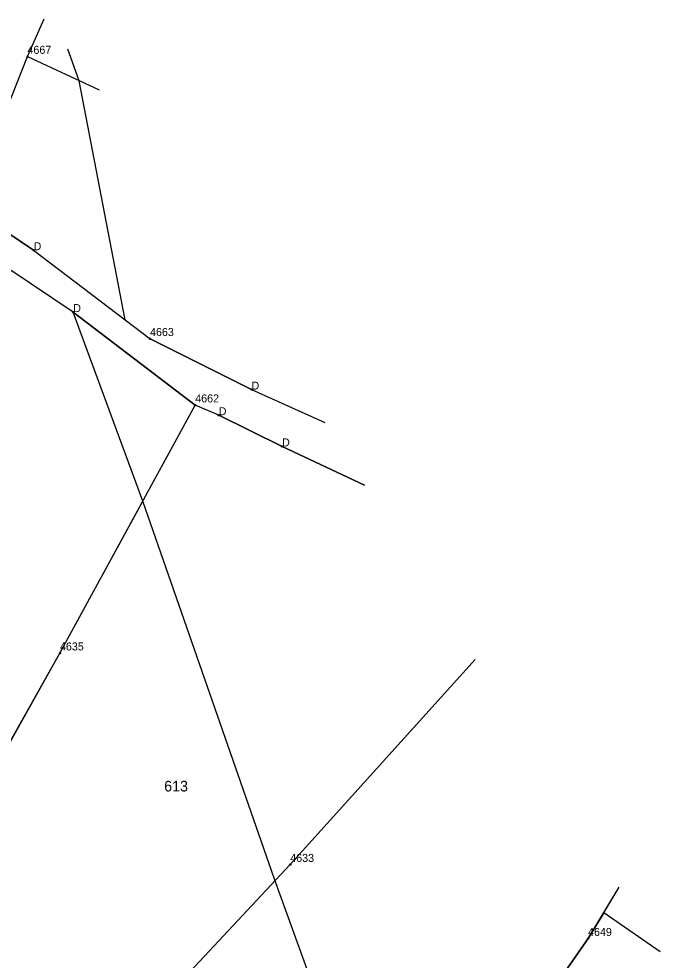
# Model space of a CAD drawing. Extents: x 7465393 to 7466459, y 5491258 to 5492404.
# Drawn here: x 7465838.7 to 7465928.8, y 5491869.8 to 5492002.2 of the extents above; entities that cross this region are included whole.
import ezdxf

# ---------------------------------------------------------------- set-up
doc = ezdxf.new("R2010")
doc.units = 0
for name, color, linetype in [('203-punkt graniczny', 7, 'Continuous'), ('203-punkt graniczny-Atr103', 7, 'Continuous'), ('211-numer działki ewidencyjnej', 7, 'Continuous'), ('217-kontur klasyfikacyjny', 7, 'Continuous'), ('218-kontur użytku gruntowego', 7, 'Continuous'), ('219-działka ewidencyjna', 7, 'Continuous')]:
    doc.layers.add(name, color=color, linetype=linetype)

# ---------------------------------------------------------------- blocks, each defined once
blk = doc.blocks.new('203')
blk.add_circle((0, 0), 0.09)

msp = doc.modelspace()

# ---------------------------------------------------------------- linework, layer by layer
at = {"layer": '217-kontur klasyfikacyjny'}
for points in [[(7465847.17, 5491993.46), (7465845.56, 5491997.89)], [(7465853.64, 5491959.84), (7465847.17, 5491993.46)], [(7465831.2, 5491976.07), (7465840.77, 5491969.64)], [(7465846.34, 5491960.94), (7465828.16, 5491973.13)], [(7465840.77, 5491969.64), (7465853.64, 5491959.84)], [(7465856.12, 5491934.36), (7465846.34, 5491960.94)], [(7465863.48, 5491947.86), (7465846.34, 5491960.94)], [(7465853.64, 5491959.84), (7465857.13, 5491957.19)], [(7465857.13, 5491957.19), (7465871.4, 5491950.04)], [(7465871.4, 5491950.04), (7465881.72, 5491945.4)], [(7465866.79, 5491946.44), (7465863.48, 5491947.86)], [(7465875.69, 5491942.06), (7465866.79, 5491946.44)], [(7465887.28, 5491936.61), (7465875.69, 5491942.06)], [(7465874.63, 5491881.21), (7465856.12, 5491934.36)], [(7465890.11, 5491838.48), (7465874.63, 5491881.21)]]:
    msp.add_lwpolyline(points, dxfattribs=at)
at = {"layer": '218-kontur użytku gruntowego'}
for points in [[(7465831.2, 5491976.07), (7465840.77, 5491969.64)], [(7465846.34, 5491960.94), (7465828.16, 5491973.13)], [(7465840.77, 5491969.64), (7465853.64, 5491959.84)], [(7465856.12, 5491934.36), (7465846.34, 5491960.94)], [(7465863.48, 5491947.86), (7465846.34, 5491960.94)], [(7465853.64, 5491959.84), (7465857.13, 5491957.19)], [(7465857.13, 5491957.19), (7465871.4, 5491950.04)], [(7465871.4, 5491950.04), (7465881.72, 5491945.4)], [(7465866.79, 5491946.44), (7465863.48, 5491947.86)], [(7465875.69, 5491942.06), (7465866.79, 5491946.44)], [(7465887.28, 5491936.61), (7465875.69, 5491942.06)], [(7465844.47, 5491912.99), (7465856.12, 5491934.36)], [(7465836.83, 5491899.38), (7465844.47, 5491912.99)], [(7465920.9, 5491876.48), (7465923.08, 5491880.07)], [(7465920.9, 5491876.48), (7465918.7, 5491872.85)], [(7465928.84, 5491870.98), (7465920.9, 5491876.48)], [(7465918.7, 5491872.85), (7465907.11, 5491856.18)]]:
    msp.add_lwpolyline(points, dxfattribs=at)
at = {"layer": '219-działka ewidencyjna'}
for points in [[(7465839.9, 5491996.87), (7465842.24, 5492002.17)], [(7465834.13, 5491982.39), (7465839.9, 5491996.87)], [(7465839.9, 5491996.87), (7465849.98, 5491992.2)], [(7465840.77, 5491969.64), (7465831.2, 5491976.07)], [(7465846.34, 5491960.94), (7465828.16, 5491973.13)], [(7465840.77, 5491969.64), (7465857.13, 5491957.19)], [(7465846.34, 5491960.94), (7465863.48, 5491947.86)], [(7465871.4, 5491950.04), (7465857.13, 5491957.19)], [(7465871.4, 5491950.04), (7465881.72, 5491945.4)], [(7465844.47, 5491912.99), (7465863.48, 5491947.86)], [(7465866.79, 5491946.44), (7465863.48, 5491947.86)], [(7465866.79, 5491946.44), (7465875.69, 5491942.06)], [(7465875.69, 5491942.06), (7465887.28, 5491936.61)], [(7465826.07, 5491880.19), (7465844.47, 5491912.99)], [(7465876.84, 5491883.26), (7465902.81, 5491912.1)], [(7465854.72, 5491859.63), (7465876.84, 5491883.26)], [(7465918.7, 5491872.85), (7465923.08, 5491880.07)], [(7465907.11, 5491856.18), (7465918.7, 5491872.85)]]:
    msp.add_lwpolyline(points, dxfattribs=at)

# ---------------------------------------------------------------- block references
at = {"layer": '203-punkt graniczny'}
for p in [(7465839.9, 5491996.87), (7465840.77, 5491969.64), (7465846.34, 5491960.94), (7465857.13, 5491957.19), (7465871.4, 5491950.04), (7465863.48, 5491947.86), (7465866.79, 5491946.44), (7465875.69, 5491942.06), (7465844.47, 5491912.99), (7465876.84, 5491883.26), (7465918.7, 5491872.85)]:
    msp.add_blockref('203', p, dxfattribs=at)

# ---------------------------------------------------------------- texts
at = {"layer": '203-punkt graniczny-Atr103'}
for s, height, p in [('4667', 1.125, (7465839.9, 5491997.25)), ('D', 1.12, (7465840.77, 5491969.64)), ('D', 1.12, (7465846.34, 5491960.94)), ('4663', 1.125, (7465857.13, 5491957.57)), ('D', 1.12, (7465871.4, 5491950.04)), ('4662', 1.125, (7465863.48, 5491948.24)), ('D', 1.12, (7465866.79, 5491946.44)), ('D', 1.12, (7465875.69, 5491942.06)), ('4635', 1.125, (7465844.47, 5491913.37)), ('4633', 1.125, (7465876.84, 5491883.64)), ('4649', 1.125, (7465918.7, 5491873.23))]:
    msp.add_text(s, height=height, dxfattribs=at).set_placement(p)
at = {"layer": '211-numer działki ewidencyjnej'}
msp.add_text('613', height=1.5, dxfattribs=at).set_placement((7465859.12, 5491893.54))

doc.saveas('drawing.dxf')
